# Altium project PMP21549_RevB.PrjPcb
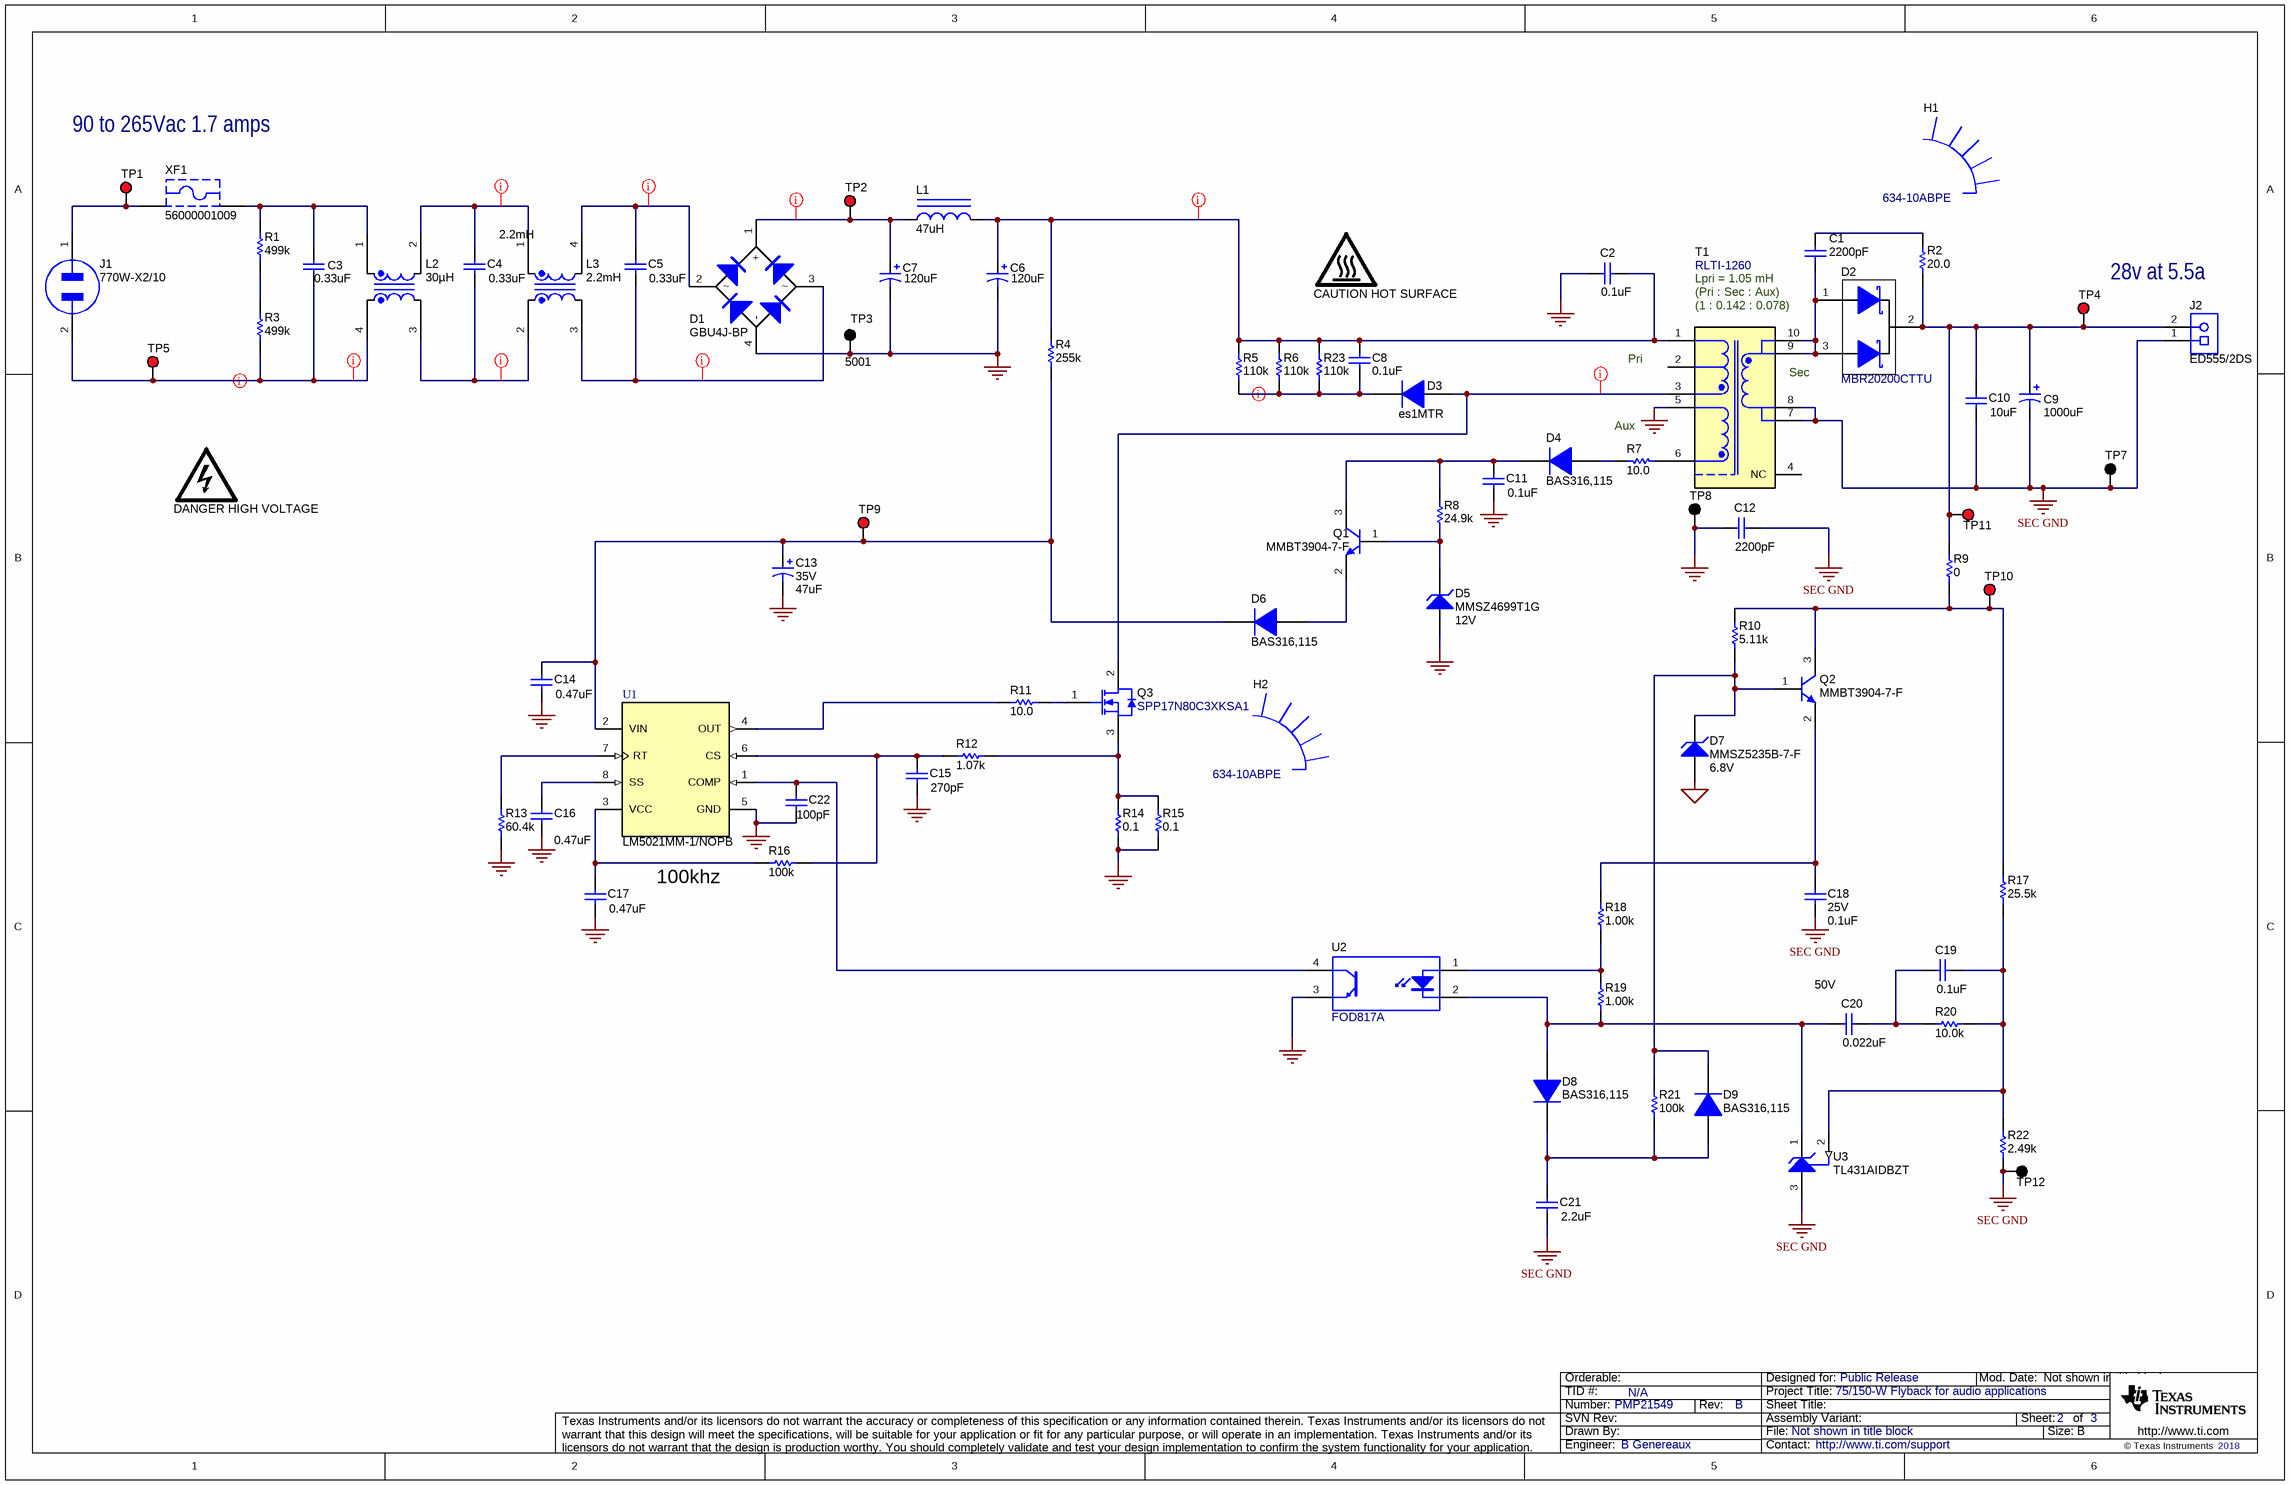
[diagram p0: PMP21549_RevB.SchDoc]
TID: N/A; TechSupport: http://www.ti.com/support; SCH_Rev: B; PRJ_Title: 75/150-W Flyback for audio applications; PRJ_Number: PMP21549; PRJ_Engineer: B Genereaux; PRJ_Customer: Public Release; PCB_Rev: B; PCB_Layout: Who did the Layout?; CopyrightYear: 2018
1 sheet, 82 parts. Net scope: global (net labels, ports and power ports of the same name join across sheets).
Board file: PMP21549_PCB_RevB.PcbDoc

## Sheet PMP21549_RevB.SchDoc
size 431 x 279 mm; Date: Not shown in title block; ApprovedBy: Not shown in title block; CheckedBy: Not shown in title block; Author: Not shown in title block; CompanyName: Not shown in title block; Engineer: Not shown in title block; Organization: Not shown in title block; Address1: Not shown in title block; Address2: Not shown in title block; Address3: Not shown in title block; Address4: Not shown in title block; DocumentNumber: 2; Revision: Use project parameter SCH_Rev; SheetNumber: 2; SheetTotal: 3; PageSetup: Record=PageOptions¦CenterHorizontal=True¦CenterVertical=True¦PrintScale=1.00¦XCorrection=1.00¦YCorrection=1.00¦PrintKind=0¦BorderSize=5000000¦LeftOffset=0¦BottomOffset=0¦Orientation=2¦PaperLength=1000¦PaperWidth=1000¦Scale=100¦PaperSource=15¦PrintQuality=600¦MediaType=1¦DitherType=10¦PaperKind=Letter¦PrintScaleMode=1

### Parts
C1  ValueDisplayed: 2200pF  [0805L]  (hidden comment: GRM21AR72E222KW01D)
C2  ValueDisplayed: 0.1uF  [1812L]  (hidden comment: GRM43DR72J104KW01L)
C3  ValueDisplayed: 0.33uF  [B32922_14.5mm]  (hidden comment: B32922C3334K)
C4  ValueDisplayed: 0.33uF  [B32922_14.5mm]  (hidden comment: B32922C3334K)
C5  ValueDisplayed: 0.33uF  [B32922_14.5mm]  (hidden comment: B32922C3334K)
C6  ValueDisplayed: 120uF  [Nichicon_2500x2500_Snap]  (hidden comment: LLS2G121MELA)
C7  ValueDisplayed: 120uF  [Nichicon_2500x2500_Snap]  (hidden comment: LLS2G121MELA)
C8  ValueDisplayed: 0.1uF  [1812L]  (hidden comment: GRM43DR72J104KW01L)
C9  ValueDisplayed: 1000uF  [FR_1250x2000]  (hidden comment: EEU-FR1V102B)
C10  ValueDisplayed: 10uF  [1206_180L]  (hidden comment: C3216X7R1V106K160AC)
C11  ValueDisplayed: 0.1uF  [0603L]  (hidden comment: 0603YC104JAT2A)
C12  ValueDisplayed: 2200pF  [DE1_900x400]  (hidden comment: DE1E3RA222MN4AN01F)
C13  VDC_V: 35V  ValueDisplayed: 47uF  [ZLJ_500x1100]  (hidden comment: 35ZLJ47MTA5X11)
C14  ValueDisplayed: 0.47uF  [0805L]  (hidden comment: 08053D474KAT2A)
C15  ValueDisplayed: 270pF  [0603L]  (hidden comment: 06035A271JAT2A)
C16  ValueDisplayed: 0.47uF  [0603L]  (hidden comment: C1608X7R1H474K080AC)
C17  ValueDisplayed: 0.47uF  [0805L]  (hidden comment: 0805YC474JAT2A)
C18  VDC_V: 25V  ValueDisplayed: 0.1uF  [0603L]  (hidden comment: C0603C104J3RACTU)
C19  ValueDisplayed: 0.1uF  [0603L]  (hidden comment: C0603C104J3RACTU)
C20  ValueDisplayed: 0.022uF  VDC_V: 50V  [0603L]  (hidden comment: C0603X223K5RACTU)
C21  ValueDisplayed: 2.2uF  [0805_150]  (hidden comment: 08053C225KAT2A)
C22  ValueDisplayed: 100pF  [0603L]  (hidden comment: 06035A101FAT2A)
D1  GBU4J-BP  [GBU]
D2  MBR20200CTTU  [TO-220AB]
D3  es1MTR  [SMA]
D4  BAS316,115  [SOD-323]
D5  MMSZ4699T1G  value 12V  [SOD-123]
D6  BAS316,115  [SOD-323]
D7  MMSZ5235B-7-F  value 6.8V  [SOD-123]
D8  BAS316,115  [SOD-323]
D9  BAS316,115  [SOD-323]
H1  634-10ABPE  [HSINK_634-10ABP]
H2  634-10ABPE  [HSINK_634-10ABP]
J1  770W-X2/10  [CONN_AC_770W-SERIES]
J2  ED555/2DS  [TERM_BLK_ED555-2DS]
L1  ValueDisplayed: 47uH  [WE-TIS-1111]  (hidden comment: 7447471470)
L2  ValueDisplayed: 30µH  [WE-CMB-NiZn-XS]  (hidden comment: 744841330)
L3  value 2.2mH  [WE-CMB_M]  (hidden comment: 744823422)
LOGO1  DANGER HIGH VOLTAGE  [IEC_HighVoltage_Large]  (no BOM)
LOGO2  CAUTION HOT SURFACE  [IEC_HotSurface_Large]  (no BOM)
Q1  MMBT3904-7-F  [SOT-23]
Q2  MMBT3904-7-F  [SOT-23]
Q3  SPP17N80C3XKSA1  [TO-220AB]
R1  ValueDisplayed: 499k  [1206L]  (hidden comment: CRCW1206499KFKEA)
R2  ValueDisplayed: 20.0  [2512L]  (hidden comment: CRCW251220R0FKEG)
R3  ValueDisplayed: 499k  [1206L]  (hidden comment: CRCW1206499KFKEA)
R4  ValueDisplayed: 255k  [0805L]  (hidden comment: CRCW0805255KFKEA)
R5  ValueDisplayed: 110k  [2512L]  (hidden comment: CRCW2512110KJNEG)
R6  ValueDisplayed: 110k  [2512L]  (hidden comment: CRCW2512110KJNEG)
R7  ValueDisplayed: 10.0  [0603L]  (hidden comment: CRCW060310R0FKEA)
R8  ValueDisplayed: 24.9k  [0603L]  (hidden comment: CRCW060324K9FKEA)
R9  ValueDisplayed: 0  [0603L]  (hidden comment: RMCF0603ZT0R00)
R10  ValueDisplayed: 5.11k  [0603L]  (hidden comment: CRCW06035K11FKEA)
R11  ValueDisplayed: 10.0  [0603L]  (hidden comment: CRCW060310R0FKEA)
R12  ValueDisplayed: 1.07k  [0603L]  (hidden comment: RT0603DRE071K07L)
R13  ValueDisplayed: 60.4k  [0603L]  (hidden comment: CRCW060360K4FKEA)
R14  ValueDisplayed: 0.1  [1206L]  (hidden comment: ERJ-8BWFR100V)
R15  ValueDisplayed: 0.1  [1206L]  (hidden comment: ERJ-8BWFR100V)
R16  ValueDisplayed: 100k  [0603L]  (hidden comment: CPF0603B100KE)
R17  ValueDisplayed: 25.5k  [0603L]  (hidden comment: RG1608P-2552-B-T5)
R18  ValueDisplayed: 1.00k  [0603L]  (hidden comment: CRCW06031K00FKEA)
R19  ValueDisplayed: 1.00k  [0603L]  (hidden comment: CRCW06031K00FKEA)
R20  ValueDisplayed: 10.0k  [0603L]  (hidden comment: ERJ-3EKF1002V)
R21  ValueDisplayed: 100k  [0603L]  (hidden comment: CRCW0603100KFKEA)
R22  ValueDisplayed: 2.49k  [0603L]  (hidden comment: CRCW06032K49FKEA)
R23  ValueDisplayed: 110k  [2512L]  (hidden comment: CRCW2512110KJNEG)
T1  RLTI-1260  [Renco_RLTI-1260]
TP1  5000  [Keystone5000]  (value not drawn)
TP2  5000  [Keystone5000]  (value not drawn)
TP3  5001  [Keystone5001]
TP4  5000  [Keystone5000]  (value not drawn)
TP5  5000  [Keystone5000]  (value not drawn)
TP7  5001  [Keystone5001]  (value not drawn)
TP8  5001  [Keystone5001]  (value not drawn)
TP9  5000  [Keystone5000]  (value not drawn)
TP10  5000  [Keystone5000]  (value not drawn)
TP11  5000  [Keystone5000]  (value not drawn)
TP12  5001  [Keystone5001]  (value not drawn)
U1  LM5021MM-1/NOPB  [DGK0008A_N]
U2  FOD817A  [DIP-4]
U3  TL431AIDBZT  [DBZ0003A_N]
XF1  56000001009  [FuseHolder_560000010]

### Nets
pwr gnd: C2.2 C6.2(-) C7.2(-) C11.2 C12.2 C13.2(-) C14.2 C15.2 C16.2 C17.2 C22.2 D1.4(-) D5.2(A) R13.1 R14.1 R15.1 T1.5(PGND) TP3.1 TP8.1 U1.5(GND) U2.3(E)
sec gnd: C9.2(-) C10.2 C12.1 C18.2 C21.2 D7.2(A) J2.1 R22.1 T1.7(SGND) T1.8(SGND) TP7.1 TP12.1 U3.3(ANODE)
NetC1_1: C1.1 R2.2
NetC1_2: C1.2 D2.1(A) D2.3(A) T1.9(28V) T1.10(28V)
NetC2_1: C2.1 C6.1(+) C8.1 L1.2 R4.2 R5.2 R6.2 R23.2 T1.1(VDC+)
NetC3_1: C3.1 L2.1 R1.2 XF1.1
NetC3_2: C3.2 J1.2(Hot) L2.4 R3.1 TP5.1
NetC4_1: C4.1 L2.2 L3.1
NetC4_2: C4.2 L2.3 L3.2
NetC5_1: C5.1 D1.2 L3.4
NetC5_2: C5.2 D1.3 L3.3
NetC7_1: C7.1(+) D1.1(+) L1.1 TP2.1
NetC8_2: C8.2 D3.1(K) R5.1 R6.1 R23.1
NetC9_1: C9.1(+) C10.1 D2.2(K) J2.2 R2.1 R9.2 TP4.1 TP11.1
NetC11_1: C11.1 D4.1(K) Q1.3(C) R8.2
NetC13_1: C13.1(+) C14.1 D6.1(K) R4.1 TP9.1 U1.2(VIN)
NetC15_1: C15.1 R12.1 R16.2 U1.6(CS)
NetC16_1: C16.1 U1.8(SS)
NetC17_1: C17.1 R16.1 U1.3(VCC)
NetC18_1: C18.1 Q2.2(E) R18.2
NetC19_1: C19.1 R17.1 R20.2 R22.2 U3.2(REF)
NetC19_2: C19.2 C20.1 R20.1
NetC20_2: C20.2 D8.2(A) R19.1 U2.2(K) U3.1(CATHODE)
NetC21_1: C21.1 D8.1(K) D9.2(A) R21.1
NetC22_1: C22.1 U1.1(COMP) U2.4(C)
NetD3_2: D3.2(A) Q3.2(D) T1.3(DRAIN)
NetD4_2: D4.2(A) R7.2
NetD5_1: D5.1(K) Q1.1(B) R8.1
NetD6_2: D6.2(A) Q1.2(E)
NetD7_1: D7.1(K) D9.1(K) Q2.1(B) R10.1 R21.2
NetJ1_1: J1.1(Neutral) TP1.1 XF1.2
NetQ2_3: Q2.3(C) R9.1 R10.2 R17.2 TP10.1
NetQ3_1: Q3.1(G) R11.2
NetQ3_3: Q3.3(S) R12.2 R14.2 R15.2
NetR1_1: R1.1 R3.2
NetR7_1: R7.1 T1.6(VCC)
NetR11_1: R11.1 U1.4(OUT)
NetR13_2: R13.2 U1.7(RT)
NetR18_1: R18.1 R19.2 U2.1(A)

Not connected (* = marked no-connect by the designer): T1 2 4(NC)

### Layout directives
rule Clearance Constraint [Clearance = 20mil]: NetC2_1, NetC3_2, NetC8_2, NetD3_2
rule Clearance Constraint [Clearance = 50mil]: NetC4_1, NetC5_1, NetC5_2, NetC7_1
rule Clearance Constraint [Clearance = 80mil]: NetC4_2

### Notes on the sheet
- 90 to 265Vac 1.7 amps
- Lpri = 1.05 mH
- (Pri : Sec : Aux)
- 28v at 5.5a
- (near T1) Pri
- (1 : 0.142 : 0.078)
- (near R7) Aux
- (near T1) Sec
- 100khz

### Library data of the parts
C1 = CMP-0008253-2: CAP, CERM, 2200 pF, 250 V, +/- 10%, X7R, 0805; Manufacturer: MuRata; TaMin_C: -55°C; Polarized: N; SizeAreaWB_mm2: 6.75; Value1: Unknown; U/M: EA; Value: 2200pF; TaMax_C: 125°C; SizeZ_mm: 1.45; SizeX_mm: 2; SizeY_mm: 1.25; Cap_Case: 0805; Value2: 250V; SizeArea_mm2: 2.5; Cap_F: 2.2nF; AEC Category: Q200
C2 C8 = CMP-0009455-2: CAP, CERM, 0.1 uF, 630 V, +/- 10%, X7R, 1812; Manufacturer: MuRata; TaMin_C: -55°C; Polarized: N; SizeAreaWB_mm2: 23.1; Value1: Unknown; U/M: EA; Value: 0.1uF; TaMax_C: 125°C; SizeZ_mm: 1.35; SizeX_mm: 4.5; SizeY_mm: 3.2; Cap_Case: 1812; Value2: 630V; SizeArea_mm2: 14.4; Cap_F: 100nF; AEC Category: Q200
C3-C5 = CMP-0012409-3: CAP, Film, 0.33 uF, 630 V, +/- 10%, TH; Manufacturer: TDK; TaMin_C: -40°C; Polarized: N; SizeAreaWB_mm2: 210; Value1: Unknown; Value: 0.33uF; TaMax_C: 110°C; SizeZ_mm: 14.5; SizeX_mm: 18; SizeY_mm: 8.5; Cap_Case: 18x8x14.5mm; Value2: 630V; SizeArea_mm2: 153; Cap_F: 330nF; AEC Category: Q200
C6 C7 = CMP-0010069-2: CAP, AL, 120 uF, 400 V, +/- 20%, TH; Manufacturer: Nichicon; TaMin_C: -25°C; Polarized: Y; SizeAreaWB_mm2: 729; Value1: Unknown; U/M: EA; Value: 120uF; TaMax_C: 85°C; SizeZ_mm: 27; SizeX_mm: 25; Cap_Case: 25x25mm; Value2: 400V; SizeArea_mm2: 625; CompType: Capacitor; AEC Qualified: N; Cap_F: 120µF; IRMS_A: 1.13A; AEC Category: Q200
C9 = CMP-0010351-2: CAP, AL, 1000 uF, 35 V, +/- 20%, 0.018 ohm, TH; Manufacturer: Panasonic; TaMin_C: -40°C; ESR_ohm: 0.018; Polarized: Y; SizeAreaWB_mm2: 210.25; U/M: EA; Value: 1000uF; TaMax_C: 105°C; SizeZ_mm: 22; SizeX_mm: 12.5; Cap_Case: 12.5x20mm; Value2: 35V; SizeArea_mm2: 156.25; CompType: Capacitor; AEC Qualified: N; Cap_F: 1mF; IRMS_A: 2.6A; AEC Category: Q200
C10 = CMP-0008705-2: CAP, CERM, 10 uF, 35 V, +/- 10%, X7R, 1206; Manufacturer: TDK; TaMin_C: -55°C; ESR_ohm: 2.229m; Polarized: N; SizeAreaWB_mm2: 10.92; Value1: 0.002229 ohm; U/M: EA; Value: 10uF; TaMax_C: 125°C; SizeZ_mm: 1.8; SizeX_mm: 3.2; SizeY_mm: 1.6; Cap_Case: 1206_180; Value2: 35V; SizeArea_mm2: 5.12; Cap_F: 10µF; IRMS_A: 4.85932A; AEC Category: Q200
C11 = CMP-0006808-4: CAP, CERM, 0.1 uF, 16 V, +/- 5%, X7R, 0603; Manufacturer: AVX; TaMin_C: -55°C; ESR_ohm: 0.039; Polarized: N; SizeAreaWB_mm2: 4.68; Value1: 0.039 ohm; U/M: EA; Value: 0.1uF; TaMax_C: 125°C; SizeZ_mm: 1; SizeX_mm: 1.6; SizeY_mm: 0.8; Cap_Case: 0603; Value2: 16V; SizeArea_mm2: 1.28; Cap_F: 100nF; AEC Category: Q200
C12 = CMP-0086279-1: CAP, CERM, 2200 pF, 250 V,+/- 20%, E, Dia 9mm; Manufacturer: MuRata; SizeX_mm: 10.6; AEC Qualified: N; SizeY_mm: 4; Value: 2200pF; U/M: EA; AEC Category: Q200; TaMax_C: 125°C; Cap_Case: 9x4mm; VDC_V: 250V; Polarized: Y; SizeZ_mm: 12; TaMin_C: -40°C; SizeArea_mm2: 42.4; SizeAreaWB_mm2: 75.6; Cap_F: 2.2nF
C13 = CMP-0010299-2: CAP, AL, 47 uF, 35 V, +/- 20%, 0.4 ohm, TH; Manufacturer: Rubycon; TaMin_C: -40°C; ESR_ohm: 0.4; Polarized: Y; SizeAreaWB_mm2: 49; Value1: 0.4 ohm; U/M: EA; Value: 47uF; TaMax_C: 105°C; SizeZ_mm: 12.5; SizeX_mm: 5; Cap_Case: 5x11mm; SizeArea_mm2: 25; CompType: Capacitor; AEC Qualified: N; Cap_F: 47µF; IRMS_A: 450mA; AEC Category: Q200
C14 = CMP-0007576-2: CAP, CERM, 0.47 uF, 25 V, +/- 10%, X5R, 0805; Manufacturer: AVX; TaMin_C: -55°C; ESR_ohm: 0.017; Polarized: N; SizeAreaWB_mm2: 6.75; Value1: 0.017 ohm; U/M: EA; Value: 0.47uF; TaMax_C: 85°C; SizeZ_mm: 1.45; SizeX_mm: 2; SizeY_mm: 1.25; Cap_Case: 0805; Value2: 25V; SizeArea_mm2: 2.5; Cap_F: 470nF; AEC Category: Q200
C15 = CMP-0006779-4: CAP, CERM, 270 pF, 50 V, +/- 5%, C0G/NP0, 0603; Manufacturer: AVX; TaMin_C: -55°C; ESR_ohm: 0.077; Polarized: N; SizeAreaWB_mm2: 4.68; Value1: 0.077 ohm; U/M: EA; Value: 270pF; TaMax_C: 125°C; SizeZ_mm: 1; SizeX_mm: 1.6; SizeY_mm: 0.8; Cap_Case: 0603; Value2: 50V; SizeArea_mm2: 1.28; AEC Category: Q200
C16 = CMP-0007050-4: CAP, CERM, 0.47 uF, 50 V, +/- 10%, X7R, 0603; Manufacturer: TDK; TaMin_C: -55°C; ESR_ohm: 0.010974; Polarized: N; SizeAreaWB_mm2: 4.68; Value1: 0.010974 ohm; U/M: EA; Value: 0.47uF; TaMax_C: 125°C; SizeZ_mm: 1; SizeX_mm: 1.6; SizeY_mm: 0.8; Cap_Case: 0603; Value2: 50V; SizeArea_mm2: 1.28; Cap_F: 470nF; IRMS_A: 1.57483A; AEC Category: Q200
C17 = CMP-0007674-2: CAP, CERM, 0.47 uF, 16 V, +/- 5%, X7R, 0805; Manufacturer: AVX; TaMin_C: -55°C; ESR_ohm: 0.011; Polarized: N; SizeAreaWB_mm2: 6.75; Value1: 0.011 ohm; U/M: EA; Value: 0.47uF; TaMax_C: 125°C; SizeZ_mm: 1.45; SizeX_mm: 2; SizeY_mm: 1.25; Cap_Case: 0805; Value2: 16V; SizeArea_mm2: 2.5; Cap_F: 470nF; AEC Category: Q200
C18 = CMP-0006856-6: CAP, CERM, 0.1 uF, 25 V, +/- 5%, X7R, 0603; Manufacturer: Kemet; TaMin_C: -55°C; Polarized: N; SizeAreaWB_mm2: 4.68; Value1: Unknown; U/M: EA; Value: 0.1uF; TaMax_C: 125°C; SizeZ_mm: 1; SizeX_mm: 1.6; SizeY_mm: 0.8; Cap_Case: 0603; SizeArea_mm2: 1.28; Cap_F: 100nF; AEC Category: Q200
C19 = CMP-0006856-6: CAP, CERM, 0.1 uF, 25 V, +/- 5%, X7R, 0603; Manufacturer: Kemet; TaMin_C: -55°C; Polarized: N; SizeAreaWB_mm2: 4.68; Value1: Unknown; U/M: EA; Value: 0.1uF; TaMax_C: 125°C; SizeZ_mm: 1; SizeX_mm: 1.6; SizeY_mm: 0.8; Cap_Case: 0603; Value2: 25V; SizeArea_mm2: 1.28; Cap_F: 100nF; AEC Category: Q200
C20 = CMP-0006984-4: CAP, CERM, 0.022 uF, 50 V, +/- 10%, X7R, 0603; Manufacturer: Kemet; TaMin_C: -55°C; Polarized: N; SizeAreaWB_mm2: 4.68; Value1: Unknown; U/M: EA; TaMax_C: 125°C; SizeZ_mm: 1; SizeX_mm: 1.6; SizeY_mm: 0.8; Cap_Case: 0603; SizeArea_mm2: 1.28; Cap_F: 22nF; AEC Category: Q200
C21 = CMP-0007573-2: CAP, CERM, 2.2 uF, 25 V, +/- 10%, X7R, 0805; Manufacturer: AVX; TaMin_C: -55°C; Polarized: N; SizeAreaWB_mm2: 6.75; Value1: Unknown; U/M: EA; Value: 2.2uF; TaMax_C: 125°C; SizeZ_mm: 1.5; SizeX_mm: 2; SizeY_mm: 1.25; Cap_Case: 0805; Value2: 25V; SizeArea_mm2: 2.5; Cap_F: 2.2µF; AEC Category: Q200
C22 = CMP-0006762-4: CAP, CERM, 100 pF, 50 V, +/- 1%, C0G/NP0, 0603; Manufacturer: AVX; TaMin_C: -55°C; Polarized: N; SizeAreaWB_mm2: 4.68; Value1: Unknown; U/M: EA; TaMax_C: 125°C; SizeZ_mm: 1; SizeX_mm: 1.6; SizeY_mm: 0.8; Cap_Case: 0603; Value2: 50V; SizeArea_mm2: 1.28; Value: 100pF; AEC Category: Q200
D1 = CMP-0029241-3: Diode, P-N-Bridge, 600 V, 4 A, TH; Manufacturer: Micro Commercial Components; Green_Lifecycle: Not Set; Green_REACh: Incomplete; Io_A: 4A; AEC Category: Q101; SizeX_mm: 22.05; SizeY_mm: 3.43; Value2: 1V; RJC_CperW: 2.2; SizeAreaWB_mm2: 130.5915; Vr_V: 600V; SizeArea_mm2: 75.6315; SizeZ_mm: 21.55; TJmax_C: 150°C; Value: 600V
D2 = CMP-0077060-2: Diode, Schottky, 200 V, 10 A, TH; Manufacturer: Fairchild Semiconductor; SizeAreaWB_mm2: 79.3; Vr_V: 200V; SizeArea_mm2: 45.9; AEC Qualified: N; TJmax_C: 150°C; AEC Category: Q101; Value: 200V; SizeZ_mm: 19.4; Green_REACh: Incomplete; Io_A: 10A; Vf_V: 900mV; SizeY_mm: 4.5; Value2: 0.9V; Green_Lifecycle: Not Set; U/M: EA; SizeX_mm: 10.2; RJC_CperW: 1.5
D3 = CMP-0074707-2: Diode, Superfast Rectifier, 1000 V, 1 A, SMA; Manufacturer: SMC Diode Solutions; RJC_CperW: 35.0; Value2: 1.7V; SizeArea_mm2: 16.3228; SizeY_mm: 2.92; SizeZ_mm: 2.87; Value1: 1A; SizeX_mm: 5.59; SizeAreaWB_mm2: 37.3428; Value: 1000V; Vr_V: 1kV; TJmax_C: 150°C; AEC Category: Q101; AEC Qualified: N
D4 D6 D8 D9 = CMP-0029006-2: Diode, Ultrafast, 100 V, 0.25 A, SOD-323; Manufacturer: Nexperia; SizeY_mm: 1.35; Value1: 0.25A; SizeAreaWB_mm2: 8.695; SizeZ_mm: 1; Io_A: 250mA; Value2: 1.4V; SizeX_mm: 2.7; Green_REACh: Incomplete; TJmax_C: 150°C; Green_Lifecycle: Not Set; Vr_V: 100V; AEC Category: Q101; Value: 100V; SizeArea_mm2: 3.645
D5 = CMP-0005742-4: Diode, Zener, 12 V, 500 mW, SOD-123; Manufacturer: ON Semiconductor; SizeAreaWB_mm2: 13.095; Value1: 0.5W; RJA_CperW: 340; SizeX_mm: 3.85; SizeY_mm: 1.7; AEC Category: Q101; SizeZ_mm: 1.35; Power_W: 500mW; SizeArea_mm2: 6.545
D7 = CMP-0005806-3: Diode, Zener, 6.8 V, 500 mW, SOD-123; Manufacturer: Diodes Inc.; Power_W: 500mW; SizeX_mm: 3.85; SizeZ_mm: 1.35; SizeAreaWB_mm2: 13.095; Value1: 0.5W; AEC Category: Q101; RJA_CperW: 350; SizeY_mm: 1.7; SizeArea_mm2: 6.545
H1 H2 = CMP-0081782-1: HEATSINK TO-220 VERT MT BLK 1"; Manufacturer: Wakefield-Vette
J1 = CMP-0074930-1: AC Receptacle, 2.5A, R/A, TH; Manufacturer: Qualtek Electronics Corporation; CNHeader: False; Green_Lifecycle: Not Set; Green_REACh: Incomplete
J2 = CMP-0074913-1: Terminal Block, 3.5mm Pitch, 2x1, TH; Manufacturer: On-Shore Technology; Cert_VDE: Y; CNHeader: False; Current_A: 6A; Green_Lifecycle: Active; Shrouded: N; Gender: Female; Green_REACh: Passed; Voltage_V: 150V; Row_Count: 1; Pitch_mm: 3.5; ContactFinish: Brass; CT: True
L1 = CMP-0064522-2: Inductor, Shielded Drum Core, Metal Composite, 47 uH, 2.5 A, 0.074 ohm, TH; Manufacturer: Wurth Elektronik; Isat: 2.5A @ 10% inductance drop; Irms: 3A @ 40C rise; Green_Lifecycle: Active; SizeAreaWB_mm2: 169; DCR_ohm: 0.074; Green_REACh: Passed; Value: 47uH; Imax_A: 2.5A; SizeZ_mm: 11.5; SizeX_mm: 11; SizeArea_mm2: 121; Ind_H: 47µH; AEC Category: Q200
L2 = CMP-0086201-1: Coupled inductor, 30 µH, 0.026 ohm, TH; Manufacturer: Wurth Elektronik; SizeArea_mm2: 120; AEC Qualified: N; SizeY_mm: 16; SizeX_mm: 7.5; AEC Category: Q200; DCR_ohm: 0.026; SizeAreaWB_mm2: 171; SizeZ_mm: 17.5; Value: 30uH
L3 = CMP-0086200-1: Coupled inductor, 2.2 mH, 0.03 ohm, TH; Manufacturer: Wurth Elektronik; SizeY_mm: 17; AEC Qualified: N; SizeX_mm: 25; SizeArea_mm2: 425; DCR_ohm: 0.03; AEC Category: Q200; SizeAreaWB_mm2: 513; SizeZ_mm: 26.5
LOGO1 = CMP-0074835-1: IEC 61010-1 High Voltage Warning; SymbolCreator: a0412235
LOGO2 = CMP-0074837-1: IEC 61010-1 Hot Surface Warning; SymbolCreator: a0412235
Q1 Q2 = CMP-0000387-2: Transistor, NPN, 40 V, 0.2 A, SOT-23; Manufacturer: Diodes Inc.; TaMax_C: 150°C; Value2: 400; Value1: 0.2 A; Vcesat1_V: 200mV; SizeX_mm: 2.5; SizeY_mm: 3; TaMin_C: -55°C; IcRated_A: 200mA; CompType: BJT; SizeZ_mm: 1.1; Value: 40 V; SizeArea_mm2: 7.5; NPN: 1; Vceo_V: 40V; PNP: 0; AEC Category: Q101; SizeAreaWB_mm2: 14; U/M: EA
Q3 = CMP-0001273-3: MOSFET, N-CH, 800 V, 17 A, TO-220AB; Alternate Manufacturer: None; Manufacturer: Infineon Technologies; SizeZ_mm: 19.4; ChType: N; Value2: 64 nC; VdsMax_V: 800V; SizeX_mm: 10.2; SizeY_mm: 4.5; Vgs_V: 20V; Value: 800V; SizeArea_mm2: 45.9; AEC Category: Q101; IdsMax_A: 17A; SizeAreaWB_mm2: 79.3; U/M: EA; QgTyp_nC: 64
R1 R3 = CMP-0017016-3: RES, 499 k, 1%, 0.25 W, AEC-Q200 Grade 0, 1206; Manufacturer: Vishay-Dale; Power_W: 250mW; TempCo: 100 ppm/C; Value: 499k; EIA_Code: E96; SizeX_mm: 3.2; SizeY_mm: 1.6; SizeZ_mm: 1.35; Value2: 0.25W; SizeArea_mm2: 5.12; AEC Qualified: Y; VDC_V: 200V; AEC Category: Q200; AEC Grade: 0
R2 = CMP-0015531-3: RES, 20.0, 1%, 1 W, AEC-Q200 Grade 0, 2512; Manufacturer: Vishay-Dale; Power_W: 1W; TempCo: 100 ppm/C; Value_Code: 20R0; Value: 20.0; EIA_Code: E96; Res_ohm: 20; SizeX_mm: 6.3; SizeY_mm: 3.2; SizeZ_mm: 0.71; SizeArea_mm2: 20.16; AEC Qualified: Y; VDC_V: 500V; AEC Grade: 0; AEC Category: Q200
R4 = CMP-0021078-3: RES, 255 k, 1%, 0.125 W, AEC-Q200 Grade 0, 0805; Manufacturer: Vishay-Dale; Power_W: 125mW; TempCo: 100 ppm/C; Value: 255k; EIA_Code: E96; SizeX_mm: 2; SizeY_mm: 1.25; SizeZ_mm: 1.45; Value2: 0.125W; SizeArea_mm2: 2.5; AEC Qualified: Y; VDC_V: 150V; AEC Category: Q200; AEC Grade: 0
R5 R6 R23 = CMP-0015871-3: RES, 110 k, 5%, 1 W, AEC-Q200 Grade 0, 2512; Manufacturer: Vishay-Dale; Power_W: 1W; TempCo: 200 ppm/C; Value: 110k; EIA_Code: E24; SizeX_mm: 6.3; SizeY_mm: 3.2; SizeZ_mm: 0.71; SizeArea_mm2: 20.16; AEC Qualified: Y; VDC_V: 500V; AEC Grade: 0; AEC Category: Q200
R7 R11 = CMP-0022003-3: RES, 10.0, 1%, 0.1 W, 0603; Manufacturer: Vishay-Dale; Power_W: 100mW; TempCo: 100 ppm/C; Value_Code: 10R0; U/M: EA; Value: 10.0; EIA_Code: E96; Res_ohm: 10; SizeX_mm: 1.6; SizeY_mm: 0.8; SizeZ_mm: 1; Value2: 0.1W; SizeArea_mm2: 1.28; VDC_V: 75V; AEC Category: Q200
R8 = CMP-0022237-3: RES, 24.9 k, 1%, 0.1 W, 0603; Manufacturer: Vishay-Dale; Power_W: 100mW; TempCo: 100 ppm/C; Value_Code: 24k9; U/M: EA; Value: 24.9k; EIA_Code: E96; SizeX_mm: 1.6; SizeY_mm: 0.8; SizeZ_mm: 1; Value2: 0.1W; SizeArea_mm2: 1.28; VDC_V: 75V; AEC Category: Q200
R9 = CMP-0023343-3: RES, 0, 1%, 0.1 W, AEC-Q200 Grade 0, 0603; Manufacturer: Stackpole Electronics Inc; Power_W: 100mW; TempCo: ppm/C; U/M: EA; Value: 0; SizeX_mm: 1.6; SizeY_mm: 0.8; SizeZ_mm: 1; Value2: 0.1W; SizeArea_mm2: 1.28; AEC Qualified: Y; AEC Category: Q200
R10 = CMP-0022509-3: RES, 5.11 k, 1%, 0.1 W, 0603; Manufacturer: Vishay-Dale; Power_W: 100mW; TempCo: 100 ppm/C; Value_Code: 5k11; U/M: EA; Value: 5.11k; EIA_Code: E96; SizeX_mm: 1.6; SizeY_mm: 0.8; SizeZ_mm: 1; Value2: 0.1W; SizeArea_mm2: 1.28; VDC_V: 75V; AEC Category: Q200
R12 = CMP-0024800-3: RES, 1.07 k, 0.5%, 0.1 W, 0603; Manufacturer: Yageo America; Power_W: 100mW; TempCo: 50 ppm/C; Value_Code: 1k07; U/M: EA; Value: 1.07k; EIA_Code: E192; SizeX_mm: 1.6; SizeY_mm: 0.8; SizeZ_mm: 1; Value2: 0.1W; SizeArea_mm2: 1.28; VDC_V: 75V; AEC Category: Q200
R13 = CMP-0022532-3: RES, 60.4 k, 1%, 0.1 W, 0603; Manufacturer: Vishay-Dale; Power_W: 100mW; TempCo: 100 ppm/C; Value_Code: 60k4; U/M: EA; Value: 60.4k; EIA_Code: E96; SizeX_mm: 1.6; SizeY_mm: 0.8; SizeZ_mm: 1; Value2: 0.1W; SizeArea_mm2: 1.28; VDC_V: 75V; AEC Category: Q200
R14 R15 = CMP-0017279-2: RES, 0.1, 1%, 0.5 W, 1206; Manufacturer: Panasonic; Power_W: 500mW; TempCo: 150 ppm/C; Value_Code: R100; U/M: EA; Value: 0.1; EIA_Code: E96; SizeX_mm: 3.2; SizeY_mm: 1.6; SizeZ_mm: 1.35; Value2: 0.5W; SizeArea_mm2: 5.12; VDC_V: 0V; AEC Category: Q200
R16 = CMP-0023346-3: RES, 100 k, 0.1%, 0.063 W, 0603; Manufacturer: TE Connectivity; Power_W: 63mW; TempCo: 25 ppm/C; U/M: EA; Value: 100k; EIA_Code: E192; SizeX_mm: 1.6; SizeY_mm: 0.8; SizeZ_mm: 1; Value2: 0.063W; SizeArea_mm2: 1.28; VDC_V: 50V; AEC Category: Q200
R17 = CMP-0023492-3: RES, 25.5 k, 0.1%, 0.1 W, 0603; Manufacturer: Susumu Co Ltd; Power_W: 100mW; TempCo: 25 ppm/C; Value_Code: 25k5; U/M: EA; Value: 25.5k; EIA_Code: E192; SizeX_mm: 1.6; SizeY_mm: 0.8; SizeZ_mm: 1; Value2: 0.1W; SizeArea_mm2: 1.28; VDC_V: 75V; AEC Category: Q200
R18 R19 = CMP-0022109-4: RES, 1.00 k, 1%, 0.1 W, 0603; Manufacturer: Vishay-Dale; Power_W: 100mW; TempCo: 100 ppm/C; Value_Code: 1k00; U/M: EA; Value: 1.00k; EIA_Code: E96; Res_ohm: 1k; SizeX_mm: 1.6; SizeY_mm: 0.8; SizeZ_mm: 1; Value2: 0.1W; SizeArea_mm2: 1.28; VDC_V: 75V; AEC Category: Q200
R20 = CMP-0022684-3: RES, 10.0 k, 1%, 0.1 W, 0603; Manufacturer: Panasonic; Power_W: 100mW; TempCo: 100 ppm/C; Value_Code: 10k0; U/M: EA; Value: 10.0k; EIA_Code: E96; Res_ohm: 10k; SizeX_mm: 1.6; SizeY_mm: 0.8; SizeZ_mm: 1; Value2: 0.1W; SizeArea_mm2: 1.28; VDC_V: 75V; AEC Category: Q200
R21 = CMP-0021990-3: RES, 100 k, 1%, 0.1 W, 0603; Manufacturer: Vishay-Dale; Power_W: 100mW; TempCo: 100 ppm/C; U/M: EA; Value: 100k; EIA_Code: E96; SizeX_mm: 1.6; SizeY_mm: 0.8; SizeZ_mm: 1; Value2: 0.1W; SizeArea_mm2: 1.28; VDC_V: 75V; AEC Category: Q200
R22 = CMP-0022277-3: RES, 2.49 k, 1%, 0.1 W, 0603; Manufacturer: Vishay-Dale; Power_W: 100mW; TempCo: 100 ppm/C; Value_Code: 2k49; U/M: EA; Value: 2.49k; EIA_Code: E96; SizeX_mm: 1.6; SizeY_mm: 0.8; SizeZ_mm: 1; Value2: 0.1W; SizeArea_mm2: 1.28; VDC_V: 75V; AEC Category: Q200
T1 = CMP-0078825-2: Transformer, 1050 uH, TH; Manufacturer: Renco Electronics; SizeAreaWB_mm2: 1053.3375; SizeArea_mm2: 927.4175; AEC Qualified: N; Lp: 1050; AEC Category: Q200; Value: 1.05mH; SizeZ_mm: 29.21; Ns1toNp: 0.142; LeakageInd_H: 6µH; Rsec1_ohm: 0.025; DCR_ohm: 0.71; SizeX_mm: 31.75
TP1 TP2 TP4 TP5 TP9-TP11 = CMP-0055137-1: Test Point, Miniature, Red, TH; Manufacturer: Keystone; CNHeader: FALSE; Green_Lifecycle: Active; Green_REACh: Passed; ContactFinish: Silver; CT: TRUE
TP3 TP7 TP8 TP12 = CMP-0055138-1: Test Point, Miniature, Black, TH; Manufacturer: Keystone; CNHeader: FALSE; Green_Lifecycle: Active; Green_REACh: Passed; ContactFinish: Silver; CT: TRUE
U1 = CMP-0072830-2: AC-DC Current Mode PWM Controller, DGK0008A (VSSOP-8); Manufacturer: Texas Instruments; CompType: IC; AEC Category: Q200; AEC Qualified: N; SizeAreaWB_mm2: 23.6; SizeArea_mm2: 14.7; SizeX_mm: 4.9; SizeY_mm: 3; SizeZ_mm: 1.1
U2 = CMP-0006173-3: Optocoupler, 5 kV, 80-160% CTR, TH; Manufacturer: Fairchild Semiconductor; CTR (Max): 160%; SizeAreaWB_mm2: 71.064; CTR (Min): 80%; SizeZ_mm: 5; SizeX_mm: 8.8; SizeY_mm: 4.58; SizeArea_mm2: 40.304; Voltage_Isolation_Vrms: 5kV
U3 = CMP-0033091-1: Adjustable Precision Shunt Regulator, 34 ppm / degC, 100 mA, -40 to 85 degC, 3-pin SOT-23 (DBZ), Green (RoHS & no Sb/Br); Manufacturer: Texas Instruments; Temp Coeff(Typ)(ppm/ degree C): 34; SubFamily: Shunt Voltage Reference; Min Iz for Regulation(uA): 600; Iout/Iz(Max)(mA): 100; VO Adj(Min)(V): 2.495; Rating: Catalog; VO Adj(Max)(V): 36; Temp Coeff(Max)(ppm/ degree C): 92; Initial Accuracy @ 25/deg C(%): 1
XF1 = CMP-0003627-1: Fuse Holder, TR5, TH; Manufacturer: Littelfuse

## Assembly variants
001: not fitted C19 R15 R19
